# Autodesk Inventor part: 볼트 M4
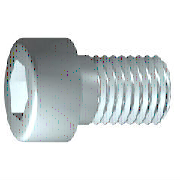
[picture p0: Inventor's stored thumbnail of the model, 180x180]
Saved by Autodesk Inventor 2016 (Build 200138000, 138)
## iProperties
IsCustomPart: 0
Created: 2009-02
Part Number: 볼트 M4
Material: 강철, 연강
Description: 6각머리 태핑 나사
Document SubType Name: Modeling
Standard: KS B 1003
Standards Organization: KS
Language: ko-KR
Size Designation: M 4 x 12
Categories: <MemberInstance><Categories><Category DisplayName="조임쇠" InternalName="e4da775c-781d-43d5-af7c-5136215cf5a6" Mnemonic="FSTN"><Category DisplayName="볼트" InternalN
Density: 1 g/cm^3
Appearance: 차가운 흰색
Author: pww
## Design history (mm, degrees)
sketch "스케치1"
  geometry: L1 (-1, 0)-(12, 0); L2 (12, 0)-(12, 2); L3 (12, 2)-(1.75, 2); L4 (1.75, 2)-(1.32, 2); L5 (1.32, 2)-(0, 2); L6 (0, 2)-(0, 3.5); L7 (0, 3.5)-(-4, 3.5); L8 (-4, 3.5)-(-4, 1.732); L9 (-4, 1.732)-(-2, 1.732); L10 (-2, 1.732)-(-1, 0); L11 (-7.2, 0)-(15.2, 0) reference; L12 (0, -0.7)-(0, 4.2) reference; L13 (1.75, 2)-(0, 2)
  constraints: 22 end point, 6 parallel, 2 collinear, 2 perpendicular, 1 horizontal, 1 point on line
  dimensions: "d1" = 10.25 distance from line of L3.end L2 (= GEL); "d2" = 0.42952 distance of L4.end L3.end (computed from GAL); "d3" = 4 distance between parallel lines of L8 L6 (= KOH); "d4" = 2 distance of L8.end L9.end (= INTI); "d5" = 60 deg angle of L10 L1; "d6" = 4 diameter of L3 L1 (= GD); "d7" = 4 diameter of L5 L1 (= BDM); "d8" = 3.4641 diameter of L9 L1 (= 1.1547 x SW); "d9" = 7 diameter of L7 L1 (= KOD); "d26" = 12 distance between parallel lines of L12 L2 (= NLG)
revolve "본체" sketch "스케치1" stored, may be unused: angle "d10" = 90 deg
sketch "스케치2"
  geometry: L1 (0, -4.9)-(0, 4.9) reference; L2 (-4.9, 0)-(4.9, 0) reference; L3 (1.732, 0)-(0.866, -1.5); L4 (0.866, -1.5)-(-0.866, -1.5); L5 (-0.866, -1.5)-(-1.732, 0); L6 (-1.732, 0)-(-0.866, 1.5); L7 (-0.866, 1.5)-(0.866, 1.5); L8 (0.866, 1.5)-(1.732, 0); 2 further points
  constraints: 12 end point, 1 coincident, 1 horizontal alignment, 1 point on line, 12 other
extrude "슬롯" join sketch "스케치2" stored distance "d11" = 10; taper "d12" = 0 deg
workplane "Work Plane1"
fillet "Fillet2" dims "d30" = 0.1 (= R)
body "Solid1"
fillet "모깎기1" dims "d17" = 0.4 (= RR)
feature "스레드" dims "d13" = 10.25 (= GEL), "d14" = 0
chamfer "모따기1" distance "d15" = 0.42941 (= -0.5 x SPD + 0.5 x GD); stored, may be unused: second distance "d16" = 0.42941 (= GUL), angle "d27" = 45 deg
other parameters: "GD" = 4 (= NND) [user parameter; used in 2 equation terms], "NLG" = 12 [user parameter; used in 1 equation term], "GEL" = 10.25 [user parameter; used in 2 equation terms], "KOD" = 7 [user parameter; used in 1 equation term], "KOH" = 4 [user parameter; used in 1 equation term], "INTI" = 2 [user parameter; used in 1 equation term], "GAL" = 0.42941 (= 0.61345 x PTC) [user parameter; used in 1 equation term], "GUL" = 0.42941 (= 0.61345 x PTC) [user parameter; used in 1 equation term], "BDM" = 4 (= NND) [user parameter; used in 1 equation term], "SW" = 3 [user parameter; used in 2 equation terms], "RR" = 0.4 [user parameter; used in 1 equation term], "SPD" = 3.14117 (= NND - 1.2269 x PTC) [user parameter; used in 1 equation term], "d19" = 0, "d28" = 0, "d29" = 0, "R" = 0.1 [user parameter; used in 1 equation term], "PHH" = 0.2 [user parameter], "GD1" = 3.14117 (= THREADDIA - 1.2269 x PTC) [user parameter], "THREADDIA" = 4 [user parameter; used in 1 equation term], "FAWI" = 45 deg [user parameter], "TPU" = 14.28571 (computed from PTC) [user parameter], "PTC" = 0.7 [user parameter; used in 5 equation terms], "NND" = 4 [user parameter; used in 3 equation terms], "TOA" = 30 deg [user parameter], "E0" = 3.465 (= 1.155 x SW) [user parameter]
